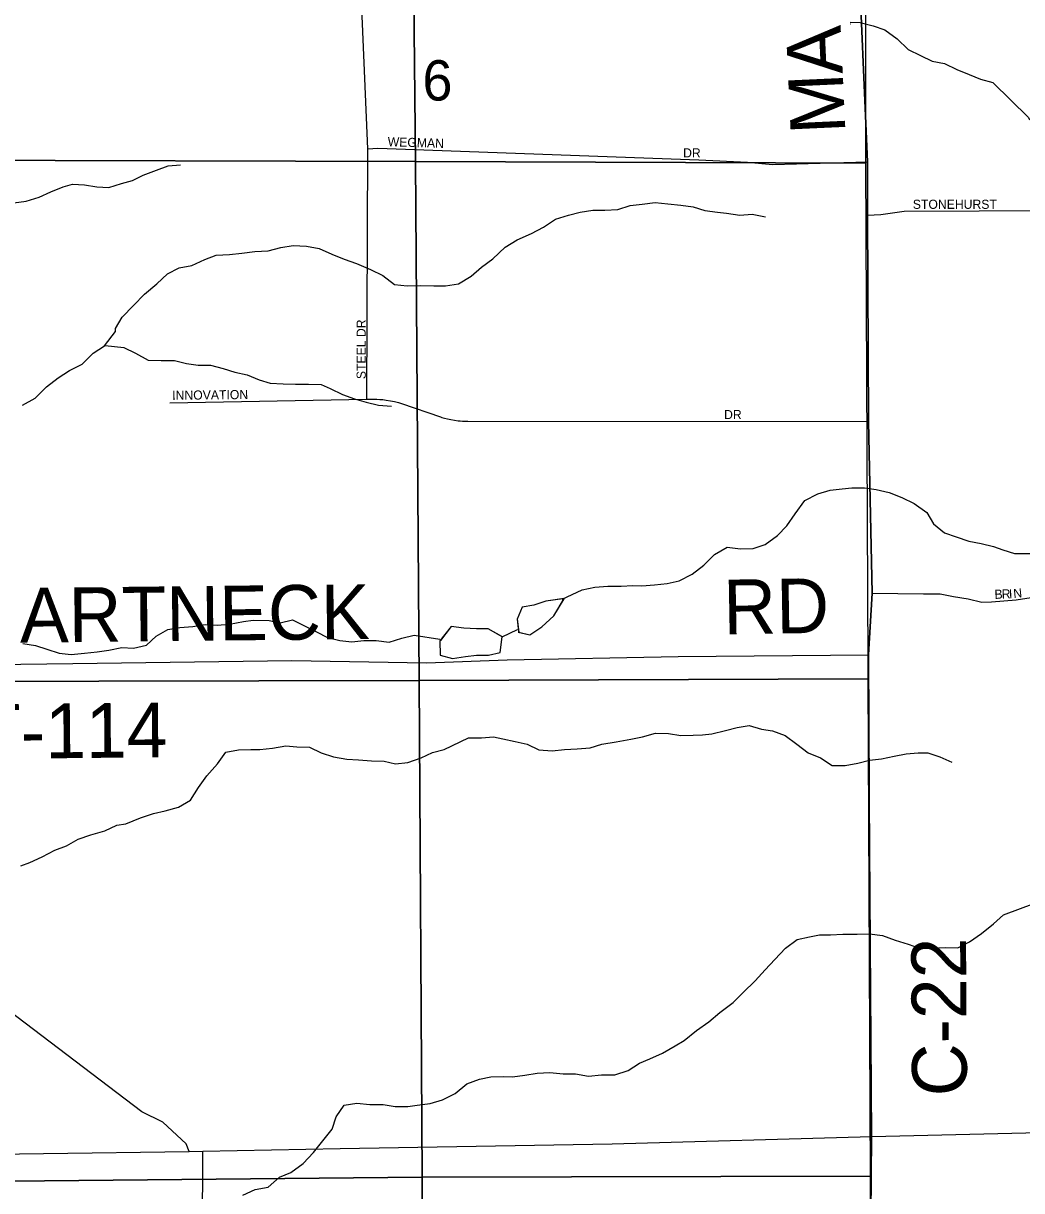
# Model space of a CAD drawing. Extents: x 1985906 to 2277390, y 930619 to 1324581.
# Drawn here: x 2134931 to 2140400, y 1179804 to 1186203 of the extents above; entities that cross this region are included whole.
import ezdxf

# ---------------------------------------------------------------- set-up
doc = ezdxf.new("R2010")
doc.units = 0
for name, color, linetype in [('GM_X_County_Road', 7, 'Continuous'), ('GM_X_County_Road_Text', 7, 'Continuous'), ('GM_X_Minor_Lake', 7, 'Continuous'), ('GM_X_Minor_River', 7, 'Continuous'), ('GM_X_Section', 7, 'Continuous'), ('GM_X_Section_Text', 7, 'Continuous'), ('GM_X_State_Route', 7, 'Continuous'), ('GM_X_Township', 7, 'Continuous'), ('GM_X_Township_Road', 7, 'Continuous'), ('GM_X_Township_Road_Text', 7, 'Continuous'), ('GM_X_Township_Subdivision', 7, 'Continuous'), ('GM_X_Township_Subdivision_Text', 7, 'Continuous')]:
    doc.layers.add(name, color=color, linetype=linetype)

msp = doc.modelspace()

# ---------------------------------------------------------------- linework, layer by layer
at = {"layer": 'GM_X_County_Road'}
for points in [[(2139542.3, 1185762.8), (2139503.5, 1186666), (2139494.6, 1188225.5), (2139496.8, 1188359.9), (2139502.2, 1190793.3), (2139542.7, 1193667.1)], [(2135840.4, 1180019.3), (2135823.3, 1180060.7), (2135695.6, 1180178.5), (2135581, 1180235), (2133980.5, 1181451.2), (2132625.8, 1182463.9), (2132406.3, 1182639.4), (2129738, 1184687.5), (2127246.1, 1186580.6), (2125917.8, 1187596.2)], [(2139557.2, 1184860.9), (2139556, 1185150.7), (2139556, 1185444), (2139542.3, 1185762.8)], [(2139580.5, 1180100.5), (2139561.5, 1182741.2), (2139581.4, 1183078.2), (2139560.8, 1184019.4), (2139557.2, 1184860.9)], [(2139668, 1166481.9), (2139668.5, 1166493.7), (2139656.8, 1167688.3), (2139644.7, 1169748.4), (2139611.5, 1172078.9), (2139566.5, 1174124.8), (2139551.5, 1176849.1), (2139580.5, 1180100.5)]]:
    msp.add_lwpolyline(points, dxfattribs=at)
at = {"layer": 'GM_X_Minor_Lake'}
for points in [[(2137894.5, 1183049.1), (2137794.2, 1183035), (2137727.9, 1183013.3), (2137663.6, 1183001.6), (2137637.2, 1182937.4), (2137645.3, 1182865.4)], [(2137887.7, 1183048.1), (2137794.2, 1183035), (2137727.9, 1183013.3), (2137663.6, 1183001.6), (2137637.2, 1182937.4), (2137644.9, 1182869.1)], [(2137642.7, 1182866.1), (2137707, 1182850.7), (2137771.4, 1182894.5), (2137837.9, 1182954.4), (2137894, 1183048.1)], [(2137645.3, 1182865.4), (2137707, 1182850.7), (2137771.4, 1182894.5), (2137837.9, 1182954.4), (2137894.5, 1183049.1)], [(2137554.9, 1182839.7), (2137478.5, 1182884.1), (2137414.3, 1182884.4), (2137344.2, 1182886.8), (2137276, 1182897.2), (2137213.7, 1182817.5)], [(2137552.7, 1182840.9), (2137478.5, 1182884.1), (2137414.3, 1182884.4), (2137344.2, 1182886.8), (2137276, 1182897.2), (2137215.8, 1182820.1)], [(2137213.7, 1182817.5), (2137215.1, 1182738.9), (2137283.2, 1182720.4), (2137353.4, 1182732.1), (2137413.6, 1182739.8), (2137479.8, 1182739.4), (2137544.1, 1182753.1), (2137554.9, 1182839.7)], [(2137213.7, 1182820.1), (2137215.1, 1182738.9), (2137283.2, 1182720.4), (2137353.4, 1182732.1), (2137413.6, 1182739.8), (2137479.8, 1182739.4), (2137544.1, 1182753.1), (2137554.8, 1182838.9)]]:
    msp.add_lwpolyline(points, dxfattribs=at)
at = {"layer": 'GM_X_Minor_River'}
for points in [[(2139461.6, 1186209.5), (2139515.6, 1186206.5), (2139587.7, 1186188.6), (2139651.8, 1186166.7), (2139718, 1186116.8), (2139778.2, 1186058.8), (2139846.4, 1186026.9), (2139910.5, 1185994.9), (2139978.6, 1185983.1), (2140044.8, 1185949.2), (2140112.9, 1185921.3), (2140175.1, 1185897.4), (2140243.2, 1185877.5), (2140438.2, 1185686.2), (2140443.4, 1185673.8)], [(2139462, 1186198.5), (2139461.5, 1186198.9)], [(2134879.6, 1185219.4), (2134947.7, 1185227.6), (2135017.8, 1185249.9), (2135081.8, 1185278.1), (2135149.9, 1185306.4), (2135200, 1185320.6), (2135266.1, 1185316.7), (2135334.2, 1185306.9), (2135400.3, 1185303), (2135468.4, 1185325.3), (2135528.5, 1185341.5), (2135588.5, 1185369.7), (2135660.6, 1185398), (2135724.7, 1185422.2), (2135792.8, 1185426.4)], [(2135436, 1184513.7), (2135435.5, 1184529.1), (2135473.5, 1184591.3), (2135535.5, 1184655.7), (2135595.5, 1184718), (2135663.5, 1184774.3), (2135721.5, 1184828.6), (2135785.6, 1184862.9), (2135853.7, 1184875.1), (2135925.7, 1184907.4), (2135987.8, 1184931.6), (2136059.9, 1184935.8), (2136128, 1184942), (2136200.1, 1184952.2), (2136272.2, 1184956.4), (2136342.3, 1184974.7), (2136410.4, 1184984.9), (2136482.5, 1184981.1), (2136552.6, 1184969.2), (2136620.8, 1184937.3), (2136688.9, 1184909.4), (2136757.1, 1184885.5), (2136833.3, 1184853.7), (2136901.4, 1184819.8), (2136965.6, 1184771.8), (2137033.7, 1184764), (2137105.8, 1184766.1), (2137179.9, 1184764.3), (2137244, 1184764.5), (2137316.1, 1184774.7), (2137384.2, 1184817), (2137442.2, 1184865.3), (2137504.2, 1184911.6), (2137570.3, 1184976), (2137636.3, 1185016.2), (2137714.4, 1185050.5), (2137780.4, 1185084.8), (2137846.5, 1185129.1), (2137918.6, 1185151.3), (2137982.6, 1185167.6), (2138050.7, 1185177.8), (2138116.8, 1185178), (2138188.9, 1185182.2), (2138255, 1185204.4), (2138321.1, 1185210.6), (2138393.2, 1185220.8), (2138461.3, 1185213), (2138533.4, 1185205.1), (2138601.6, 1185197.3), (2138665.7, 1185177.4), (2138733.8, 1185167.6), (2138783.9, 1185161.7), (2138856, 1185151.9), (2138924.1, 1185156.1), (2138996.3, 1185142.2)], [(2134927.5, 1184109.5), (2134995.8, 1184147.3), (2135058.3, 1184209.2), (2135122.7, 1184259.1), (2135185.1, 1184298.9), (2135253.5, 1184334.7), (2135313.9, 1184394.6), (2135376.3, 1184434.5), (2135436.1, 1184512.9)], [(2135379.6, 1184436.5), (2135482.6, 1184425.8), (2135546.6, 1184395.4), (2135614.6, 1184356.8), (2135686.8, 1184354.4), (2135759, 1184354), (2135825.1, 1184337.6), (2135889.2, 1184329.2), (2135957.4, 1184328.8), (2136025.5, 1184310.4), (2136089.6, 1184289.9), (2136157.7, 1184275.5), (2136223.8, 1184249), (2136283.9, 1184230.6), (2136354, 1184226.2), (2136422.2, 1184223.8), (2136494.4, 1184225.4), (2136562.6, 1184223), (2136612.6, 1184200.6), (2136680.7, 1184168.1), (2136744.7, 1184143.7), (2136808.8, 1184125.2), (2136876.9, 1184108.8), (2136949.1, 1184104.4)], [(2137883.5, 1183046), (2137993, 1183098.2), (2138061.3, 1183111.9), (2138133.5, 1183117.5), (2138205.7, 1183117.1), (2138269.9, 1183120.8), (2138320.1, 1183118.5), (2138388.3, 1183124.1), (2138458.5, 1183131.8), (2138524.8, 1183147.5), (2138595.1, 1183183.2), (2138659.6, 1183233.1), (2138718, 1183291), (2138786.4, 1183330.8), (2138860.6, 1183322.4), (2138928.8, 1183324), (2138995.1, 1183345.8), (2139063.5, 1183395.6), (2139113.9, 1183447.5), (2139160.4, 1183513.6), (2139212.9, 1183587.6), (2139283.3, 1183623.4), (2139351.6, 1183643.1), (2139417.8, 1183650.8), (2139470, 1183656.5), (2139540.2, 1183656.1), (2139604.3, 1183647.7), (2139674.4, 1183631.3), (2139744.5, 1183602.8), (2139812.5, 1183570.2), (2139880.5, 1183521.6), (2139918.2, 1183459.2), (2139978.2, 1183410.6), (2140042.2, 1183388.2), (2140110.3, 1183363.7), (2140178.4, 1183351.2), (2140246.5, 1183334.8), (2140296.6, 1183316.4), (2140360.7, 1183296), (2140459.5, 1183295.8)], [(2135606.8, 1182794), (2135659.2, 1182843.9), (2135723.6, 1182879.7), (2135787.8, 1182891.4), (2135860, 1182897), (2135928.3, 1182906.7), (2135992.4, 1182904.3), (2136060.7, 1182910), (2136136.9, 1182923.6), (2136191.1, 1182931.4), (2136277.4, 1182928.9), (2136337.5, 1182916.5), (2136405.7, 1182932.2), (2136467.8, 1182901.7), (2136537.8, 1182867.2), (2136597.8, 1182836.7), (2136665.9, 1182820.3), (2136730.1, 1182811.9), (2136796.3, 1182819.5), (2136864.5, 1182819.2), (2136934.6, 1182810.7), (2137004.9, 1182832.4), (2137073.2, 1182848.1), (2137213.7, 1182826.4)], [(2137554.8, 1182838.9), (2137638.6, 1182880.7)], [(2134929, 1182803.8), (2134997.1, 1182791.3), (2135059.2, 1182772.9), (2135127.2, 1182750.4), (2135193.4, 1182742), (2135265.6, 1182749.7), (2135335.9, 1182757.3), (2135400.1, 1182767), (2135470.4, 1182780.7), (2135534.5, 1182778.3), (2135606.8, 1182794)], [(2134916.9, 1181584.4), (2134967.1, 1181602.2), (2135035.4, 1181634), (2135103.8, 1181669.8), (2135168.1, 1181693.5), (2135232.5, 1181731.3), (2135300.8, 1181755.1), (2135377.1, 1181776.8), (2135443.4, 1181806.5), (2135493.6, 1181814.3), (2135574, 1181848), (2135644.3, 1181871.7), (2135708.6, 1181885.4), (2135780.9, 1181905.1), (2135847.3, 1181944.9), (2135891.7, 1182013), (2135936.2, 1182077), (2135994.7, 1182143), (2136041.1, 1182207), (2136109.4, 1182220.7), (2136177.6, 1182222.3), (2136227.7, 1182222), (2136295.9, 1182229.7), (2136370.2, 1182241.3), (2136430.4, 1182237), (2136498.5, 1182234.6), (2136562.6, 1182204.1), (2136630.6, 1182181.6), (2136702.8, 1182169.2), (2136766.9, 1182164.8), (2136839.1, 1182160.4), (2136907.3, 1182158), (2136969.4, 1182143.6), (2137037.6, 1182151.3), (2137110, 1182177), (2137172.3, 1182204.8), (2137236.6, 1182222.5), (2137369.2, 1182286), (2137441.4, 1182285.6), (2137507.7, 1182291.3), (2137557.7, 1182281), (2137625.9, 1182266.5), (2137692, 1182252.1), (2137756, 1182219.6), (2137828.2, 1182215.2), (2137896.4, 1182222.8), (2137964.6, 1182226.5), (2138036.8, 1182232.1), (2138101.1, 1182251.8), (2138179.4, 1182263.5), (2138259.7, 1182279.1), (2138323.9, 1182290.8), (2138394.3, 1182312.5), (2138466.4, 1182310.1), (2138532.6, 1182299.7), (2138600.8, 1182301.3), (2138652.9, 1182303), (2138703.1, 1182308.8), (2138777.4, 1182326.4), (2138841.7, 1182342.2), (2138907.9, 1182353.9)], [(2138907.9, 1182353.9), (2138976, 1182333.4), (2139036.1, 1182325), (2139104.2, 1182298.5), (2139168.1, 1182252), (2139230.1, 1182203.4), (2139298.1, 1182176.9), (2139362.1, 1182134.4), (2139434.3, 1182134), (2139502.5, 1182147.7), (2139566.8, 1182163.4), (2139633, 1182171.1), (2139701.3, 1182184.7), (2139767.5, 1182198.4), (2139833.8, 1182204.1), (2139885.9, 1182203.8), (2139952, 1182181.3), (2140018, 1182152.8)], [(2136133.3, 1179779.8), (2136201.6, 1179809.5), (2136271.9, 1179823.2), (2136334.3, 1179877.1), (2136396.6, 1179902.9), (2136465.1, 1179952.7), (2136521.5, 1180012.7), (2136622.5, 1180140.7), (2136644.9, 1180208.9), (2136689.3, 1180272.9), (2136757.5, 1180282.6), (2136829.7, 1180276.1), (2136901.9, 1180275.7), (2136968.1, 1180265.3), (2137038.3, 1180264.9), (2137088.4, 1180272.7), (2137160.7, 1180282.3), (2137227, 1180302.1), (2137297.3, 1180335.8), (2137361.8, 1180389.7), (2137430.1, 1180415.4), (2137492.3, 1180427.2), (2137560.5, 1180428.8), (2137610.7, 1180428.5), (2137678.9, 1180436.2), (2137747.1, 1180447.8), (2137815.4, 1180451.5), (2137889.5, 1180445.1), (2137955.7, 1180444.7), (2138027.9, 1180432.2), (2138098.1, 1180437.9), (2138172.3, 1180439.5), (2138244.6, 1180463.2), (2138307, 1180503), (2138363.3, 1180526.8), (2138433.6, 1180556.6), (2138502, 1180598.3), (2138552.3, 1180626.2), (2138618.8, 1180682.1), (2138687.2, 1180729.9), (2138747.6, 1180779.8), (2138820.1, 1180835.6), (2138874.5, 1180889.6), (2138941, 1180953.5), (2138995.5, 1181013.5), (2139047.9, 1181071.4), (2139106.4, 1181133.4), (2139170.8, 1181181.2), (2139239.1, 1181194.9), (2139293.3, 1181206.7), (2139353.4, 1181206.3), (2139421.6, 1181210), (2139499.9, 1181209.6), (2139566.1, 1181211.2), (2139638.2, 1181202.8), (2139708.3, 1181176.2), (2139778.4, 1181155.8), (2139840.4, 1181133.3), (2139908.6, 1181132.9), (2139980.8, 1181136.6), (2140051, 1181134.2), (2140115.4, 1181168), (2140179.8, 1181213.8), (2140246.2, 1181265.7), (2140300.6, 1181315.6), (2140472.8, 1181379.7)]]:
    msp.add_lwpolyline(points, dxfattribs=at)
at = {"layer": 'GM_X_Section'}
for points in [[(2136944.5, 1188308.5), (2137050, 1188308.3), (2137080.6, 1185445.8), (2134445.8, 1185453), (2134426.5, 1188313.6)], [(2139545, 1188303.3), (2139545, 1188257.3), (2139545.4, 1185435.9), (2137080.6, 1185445.8), (2137050, 1188308.3)], [(2137080.6, 1185445.8), (2137100, 1182601), (2134465.1, 1182595.3), (2134445.8, 1185453)], [(2139545.4, 1185435.9), (2139558.1, 1182700.9), (2139558.4, 1182610.1), (2137100, 1182601), (2137080.6, 1185445.8)], [(2137100, 1182601), (2137116.7, 1179878.2), (2134481.4, 1179851.9), (2134465.1, 1182595.3)], [(2139558.4, 1182610.1), (2139570, 1179882.9), (2137116.7, 1179878.2), (2137100, 1182601)], [(2137116.7, 1179878.2), (2137137.1, 1177174.3), (2134496.5, 1177169.7), (2134481.4, 1179851.9)], [(2139570, 1179882.9), (2139578.7, 1177314.5), (2139579.9, 1177178.5), (2137137.1, 1177174.3), (2137116.7, 1179878.2)]]:
    msp.add_lwpolyline(points, close=True, dxfattribs=at)
at = {"layer": 'GM_X_State_Route'}
for points in [[(2139580.5, 1180100.5), (2141190.5, 1180139.8), (2141376.4, 1180146.7)], [(2127761.1, 1179936.1), (2128863.2, 1179945.4), (2131816.4, 1179974.3), (2132685, 1179980.5), (2133468.8, 1179984.7), (2135042.6, 1180007.4), (2135840.4, 1180019.3), (2135915.3, 1180020.3), (2136666.6, 1180034.3), (2138156.6, 1180060.1), (2139580.5, 1180100.5)]]:
    msp.add_lwpolyline(points, dxfattribs=at)
at = {"layer": 'GM_X_Township'}
for points in [[(2139644.7, 1169748.4), (2139611.5, 1172078.9), (2139566.5, 1174124.9), (2139551.5, 1176849.1), (2139574.3, 1180104.3), (2139561.5, 1182741.2), (2139581.4, 1183078.2), (2139560.8, 1184019.4), (2139556, 1185150.7), (2139556, 1185444), (2139503.5, 1186666), (2139494.6, 1188225.5), (2139496.8, 1188359.9), (2139502.2, 1190793.3), (2139549.1, 1193676.6), (2140581.8, 1193696.4), (2144321.2, 1193786.8), (2145028.4, 1193800.8), (2151106.9, 1193912.6)], [(2117908.3, 1193445.4), (2126053.1, 1193488.1), (2129443.2, 1193492.7), (2134076.1, 1193549.4), (2139549.1, 1193676.6), (2139502.2, 1190793.3), (2139496.8, 1188359.9), (2139494.6, 1188225.5), (2139503.5, 1186666), (2139556, 1185444), (2139556, 1185150.7), (2139560.8, 1184019.4), (2139581.4, 1183078.2), (2139561.5, 1182741.2), (2139574.3, 1180104.3), (2139551.5, 1176849.1), (2139566.5, 1174124.9), (2139611.5, 1172078.9), (2139644.7, 1169748.4)]]:
    msp.add_lwpolyline(points, dxfattribs=at)
at = {"layer": 'GM_X_Township_Road'}
for points in [[(2132406.3, 1182639.4), (2134061, 1182678.7), (2135203, 1182693), (2136403, 1182709.7), (2137140.4, 1182697.7), (2137581.1, 1182714.2), (2138518.7, 1182731.4), (2139561.5, 1182741.2)], [(2135277.4, 1174606.2), (2135313.1, 1174647.8), (2135330.9, 1174698.4), (2135462.8, 1175279), (2135610.5, 1175929.8), (2135845.5, 1176813.2), (2135896.1, 1177000.6), (2135925.8, 1177149.3), (2135949.6, 1177307), (2135909.4, 1178670.4), (2135915.3, 1180020.3)]]:
    msp.add_lwpolyline(points, dxfattribs=at)
at = {"layer": 'GM_X_Township_Subdivision'}
for points in [[(2136812.4, 1184141.6), (2136818.4, 1185515.4), (2136777.2, 1186501.1)], [(2136818.4, 1185515.4), (2136874.3, 1185518.2), (2138631.5, 1185454.8), (2138897.8, 1185442.5), (2139038, 1185428.5), (2139556, 1185444)], [(2139556, 1185150.7), (2139629.9, 1185155.5), (2139706.3, 1185165.1), (2139756.3, 1185172.2), (2140991.4, 1185179.3), (2141017.5, 1185179.7), (2141052.1, 1185181.9), (2141059, 1185182.7), (2141071.5, 1185184.5), (2141084.8, 1185186.8), (2141102.9, 1185190.7), (2141124.1, 1185196.4), (2141137.2, 1185200.2), (2141164, 1185206.5), (2141190.1, 1185210.8), (2141205, 1185212.5), (2141229, 1185214), (2141245.1, 1185214.3), (2141260.6, 1185214.3), (2141275.4, 1185214.8)], [(2135734.1, 1184123.1), (2136812.4, 1184141.6), (2136853.6, 1184142.3), (2136868.8, 1184142.1), (2136884.8, 1184141.3), (2136901.2, 1184140), (2136919.6, 1184137.9), (2136943.1, 1184134), (2136963.9, 1184129.7), (2136986.4, 1184123.8), (2137003.8, 1184118.5), (2137216.6, 1184045.1), (2137224.2, 1184042.7), (2137238.8, 1184038.4), (2137255.2, 1184034.3), (2137273.3, 1184030.4), (2137293.2, 1184026.9), (2137313.4, 1184024.3), (2137324.2, 1184023.2), (2137337.4, 1184022.3), (2137349.7, 1184021.7), (2137365.8, 1184021.5), (2139560.8, 1184019.4)], [(2139581.4, 1183078.2), (2139862.2, 1183075.7), (2139954.9, 1183075.7), (2140027.1, 1183060.2), (2140106.9, 1183047.3), (2140181.6, 1183029.3), (2140235.7, 1183031.9), (2140369.6, 1183042.2), (2140524.2, 1183065.4)]]:
    msp.add_lwpolyline(points, dxfattribs=at)

# ---------------------------------------------------------------- texts
at = {"layer": 'GM_X_County_Road_Text'}
for s, rotation, p in [('A', 92.61282, (2139420.5, 1185927.5)), ('M', 92.61182, (2139435.4, 1185602.2)), ('C-22', 90.3429, (2140100.9, 1180321.9))]:
    msp.add_text(s, height=300, rotation=rotation, dxfattribs=at).set_placement(p)
at = {"layer": 'GM_X_Section_Text'}
msp.add_text('6', height=221, rotation=0.00001, dxfattribs=at).set_placement((2137117.9, 1185779.5))
at = {"layer": 'GM_X_Township_Road_Text'}
for s, rotation, p in [('RD', 0.98721, (2138768.1, 1182852.4)), ('HARTNECK', 0.63082, (2134623.7, 1182804)), ('T-114', 0.56142, (2134673.7, 1182169.7))]:
    msp.add_text(s, height=300, rotation=rotation, dxfattribs=at).set_placement(p)
at = {"layer": 'GM_X_Township_Subdivision_Text'}
for s, rotation, p in [('WEGMAN', 358.21105, (2136926.8, 1185529)), ('DR', 0.00001, (2138545.7, 1185467.4)), ('STONEHURST', 0.00001, (2139804.1, 1185185.8)), ('STEEL DR', 90, (2136807.1, 1184252.4)), ('INNOVATION', 0.65069, (2135747.2, 1184138.6)), ('DR', 0.00001, (2138770.1, 1184033)), ('B', 2.21006, (2140252.5, 1183047.4)), ('R', 2.1858, (2140292.1, 1183048.9)), ('I', 2.30888, (2140331.8, 1183050.5)), ('N', 5.76637, (2140357.1, 1183051.6))]:
    msp.add_text(s, height=50, rotation=rotation, dxfattribs=at).set_placement(p)

doc.saveas('drawing.dxf')
